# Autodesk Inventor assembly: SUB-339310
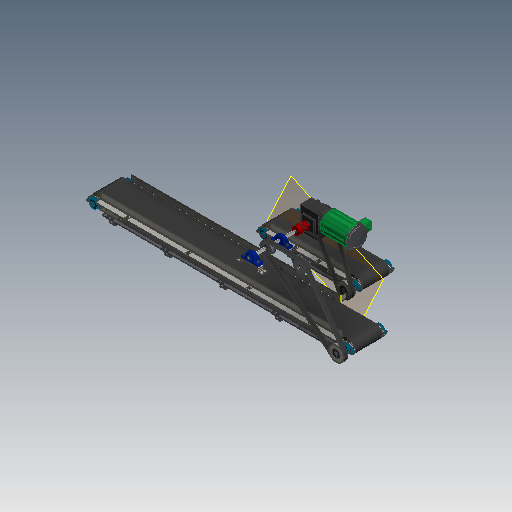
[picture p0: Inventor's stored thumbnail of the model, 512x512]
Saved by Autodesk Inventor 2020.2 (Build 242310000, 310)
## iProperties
Created: 1999-09
Part Number: SUB-339310
Document SubType Name: Assembly
Designer: Autodesk
Mass: 247650 g
Surface Area: 99527.2 cm^2
Volume: 39222.3 cm^3
Density: 6.314 g/cm^3
Control State: 0
Master: False
Checked Out: False
Shininess: 0.0
Length Units: 11269
Angle Units: 11279
Time Units: 11290
Mass Units: 11286
Length Display Precision: 3
Angle Display Precision: 2
Compacted: True
Dimensions: 2353,4x1828,9x1073,3 mm
Mass: 545,974 lb
DocNumber: SUB-339310.iam
Folder: 01 - Themengebiete\Simplification\01 - Packaging machine\
VDS_Category: 3D Komponenten
Density: 0.0
Volumn: 0.0
Area: 0.0
PropertySet Name: Model Information
Author: Autodesk
Revision Number: -
Title: SUB-339310
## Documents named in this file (35)
- D:\07 - DEMODATEN\OTX 2019 - Dataset - UPDATE - Dez2019\Designs\07-Packing machine\SUB-339310.iam
- D:\07 - DEMODATEN\OTX 2019 - Dataset - UPDATE - Dez2019\Designs\07-Packing machine\Parts\ADSK-011842.ipt
- D:\07 - DEMODATEN\OTX 2019 - Dataset - UPDATE - Dez2019\Designs\07-Packing machine\Parts\ADSK-011245.ipt
- D:\07 - DEMODATEN\OTX 2019 - Dataset - UPDATE - Dez2019\Designs\07-Packing machine\Parts\ADSK-011752.ipt
- D:\07 - DEMODATEN\OTX 2019 - Dataset - UPDATE - Dez2019\Designs\07-Packing machine\Parts\ADSK-011796.ipt
- D:\07 - DEMODATEN\OTX 2019 - Dataset - UPDATE - Dez2019\Designs\07-Packing machine\Parts\ADSK-011715.ipt
- D:\07 - DEMODATEN\OTX 2019 - Dataset - UPDATE - Dez2019\Designs\07-Packing machine\Parts\ADSK-011569.ipt
- D:\07 - DEMODATEN\OTX 2019 - Dataset - UPDATE - Dez2019\Designs\07-Packing machine\Parts\ADSK-011567.ipt
- D:\07 - DEMODATEN\OTX 2019 - Dataset - UPDATE - Dez2019\Designs\07-Packing machine\Parts\ADSK-011744.ipt
- D:\07 - DEMODATEN\OTX 2019 - Dataset - UPDATE - Dez2019\Designs\07-Packing machine\Parts\ADSK-011738.ipt
- D:\07 - DEMODATEN\OTX 2019 - Dataset - UPDATE - Dez2019\Designs\07-Packing machine\Parts\ADSK-011775.ipt
- D:\07 - DEMODATEN\OTX 2019 - Dataset - UPDATE - Dez2019\Designs\07-Packing machine\Parts\ADSK-011780.ipt
- D:\07 - DEMODATEN\OTX 2019 - Dataset - UPDATE - Dez2019\Designs\07-Packing machine\A104989.iam
- D:\07 - DEMODATEN\OTX 2019 - Dataset - UPDATE - Dez2019\Designs\07-Packing machine\Parts\ADSK-011703.ipt
- D:\07 - DEMODATEN\OTX 2019 - Dataset - UPDATE - Dez2019\Content Center Files\de-DE\DIN 125-1  B\DIN 125-1 - B 6,4.ipt
- D:\07 - DEMODATEN\OTX 2019 - Dataset - UPDATE - Dez2019\Content Center Files\de-DE\ISO 4762(2)\ISO 4762 - M6 x 20ISO.ipt
- D:\07 - DEMODATEN\OTX 2019 - Dataset - UPDATE - Dez2019\Content Center Files\de-DE\DIN 125-1  B\DIN 125-1 - B 8,4.ipt
- D:\07 - DEMODATEN\OTX 2019 - Dataset - UPDATE - Dez2019\Content Center Files\de-DE\ISO 4032(1)\ISO 4032 - M8DIN EN.ipt
- D:\07 - DEMODATEN\OTX 2019 - Dataset - UPDATE - Dez2019\Content Center Files\de-DE\ISO 4762(2)\ISO 4762 - M8 x 25ISO.ipt
- D:\07 - DEMODATEN\OTX 2019 - Dataset - UPDATE - Dez2019\Content Center Files\de-DE\ISO 4762(2)\ISO 4762 - M8 x 35ISO.ipt
- D:\07 - DEMODATEN\OTX 2019 - Dataset - UPDATE - Dez2019\Designs\07-Packing machine\ADSK-014344.iam
- D:\07 - DEMODATEN\OTX 2019 - Dataset - UPDATE - Dez2019\Content Center Files\de-DE\ISO 2491 - A\ISO 2491 - A  6 x 4 x 45.ipt
- D:\07 - DEMODATEN\OTX 2019 - Dataset - UPDATE - Dez2019\Content Center Files\de-DE\ISO 4762(2)\ISO 4762 - M8 x 40ISO.ipt
- D:\07 - DEMODATEN\OTX 2019 - Dataset - UPDATE - Dez2019\Content Center Files\de-DE\ISO 2338(2)\ISO 2338 - 10 m6 x 24.ipt
- D:\07 - DEMODATEN\OTX 2019 - Dataset - UPDATE - Dez2019\Content Center Files\de-DE\ISO 4026\ISO 4026 - M8 x 25 - ISO.ipt
- D:\07 - DEMODATEN\OTX 2019 - Dataset - UPDATE - Dez2019\Content Center Files\de-DE\ISO 4035(2)\ISO 4035 - M16 - ISO.ipt
- D:\07 - DEMODATEN\OTX 2019 - Dataset - UPDATE - Dez2019\Designs\07-Packing machine\ADSK-014353.iam
- D:\07 - DEMODATEN\OTX 2019 - Dataset - UPDATE - Dez2019\Designs\07-Packing machine\ADSK-014354.iam
- D:\07 - DEMODATEN\OTX 2019 - Dataset - UPDATE - Dez2019\Designs\07-Packing machine\Parts\ADSK-011566.ipt
- D:\07 - DEMODATEN\OTX 2019 - Dataset - UPDATE - Dez2019\Designs\07-Packing machine\Parts\ADSK-011812.ipt
- D:\07 - DEMODATEN\OTX 2019 - Dataset - UPDATE - Dez2019\Content Center Files\de-DE\ISO 4032(1)\ISO 4032 - M6DIN EN.ipt
- D:\07 - DEMODATEN\OTX 2019 - Dataset - UPDATE - Dez2019\Content Center Files\de-DE\ISO 4762(2)\ISO 4762 - M6 x 16ISO.ipt
- D:\07 - DEMODATEN\OTX 2019 - Dataset - UPDATE - Dez2019\Content Center Files\de-DE\ISO 2491 - A\ISO 2491 - A  6 x 4 x 32.ipt
- D:\07 - DEMODATEN\OTX 2019 - Dataset - UPDATE - Dez2019\Designs\07-Packing machine\Parts\ADSK-014368.ipt
- D:\07 - DEMODATEN\OTX 2019 - Dataset - UPDATE - Dez2019\Designs\07-Packing machine\Parts\ADSK-014369.ipt
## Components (170 placed, 34 different names)
1. ADSK-014354:1 [sub-assembly] — Passend:418, Fluchtend:63
2. ADSK-011569:1 — Fluchtend:43, Fluchtend:45, Fluchtend:46, Fluchtend:47, Passend:273, Mate:284
3. ADSK-011569:2 — Fluchtend:44, Fluchtend:45, Fluchtend:46, Passend:267, Passend:268, Passend:269, Passend:270, Fluchtend:49, Fluchtend:54, Passend:294
4. ADSK-011715:1 — Passend:273, Passend:279, Passend:281, Passend:283, Mate:284, Mate:285, Fluchtend:50
5. ADSK-011715:2 — Passend:268, Passend:269, Passend:270, Passend:275, Passend:277, Passend:282
6. ADSK-011796:1 — Fluchtend:48, Passend:282, Fluchtend:49, Passend:295, Passend:307, Passend:308, Passend:309, Passend:417, Passend:419, Passend:421
7. ADSK-011567:1 — Passend:283, Fluchtend:50, Passend:286, Passend:287, Passend:288, Passend:289, Fluchtend:52, Passend:296, Passend:297, Passend:298, Passend:302, Passend:303, Passend:304, Passend:305, Passend:306
8. ADSK-014344:1 [sub-assembly] — Passend:286, Fluchtend:52, Fluchtend:55, Passend:424, Fluchtend:425
9. ADSK-011703:2 — Fluchtend:53, Fluchtend:54, Einfügen:58, Passend:294
10. ADSK-011780:1 — Einfügen:58, Passend:290, Einfügen:62
11. A104989:1 [sub-assembly] — Passend:290, Passend:291, Passend:292, Einfügen:60
12. ADSK-011775:2 — Passend:291, Passend:292, Einfügen:59, Einfügen:61, Fluchtend:55, Passend:423, Fluchtend:424, Fluchtend:425
13. ADSK-011752:1 — Passend:307, Passend:308, Passend:309, Passend:318, Einfügen:67, Einfügen:73
14. ADSK-011744:1 — Passend:295, Winkel:1, Passend:300
15. ADSK-011738:1 — Passend:298, Passend:299, Passend:301, Passend:302
16. ADSK-011744:2 — Passend:296, Passend:297, Passend:299, Winkel:1, Passend:300, Passend:301, Passend:303
17. ADSK-011842:1 — Einfügen:73
18. ADSK-011245:1 — Passend:318, Einfügen:67
19. ADSK-014353:1 [sub-assembly] — Fluchtend:56, Fluchtend:57, Fluchtend:58, Passend:329, Passend:330, Fluchtend:59, Fluchtend:60, Fluchtend:61, Passend:331, Passend:332, Fluchtend:62, Fluchtend:423, Fluchtend:424
20. ADSK-011780:2 — Fluchtend:66
21. A104989:2 [sub-assembly]
22. ADSK-011703:3 — Fluchtend:64, Fluchtend:65
23. ADSK-011775:3 — Einfügen:120, Fluchtend:63, Fluchtend:66, Fluchtend:426, Fluchtend:427
24. ADSK-014344:2 [sub-assembly] — Passend:417, Passend:418, Passend:420, Fluchtend:426
25. ADSK-014368:1 — Fluchtend:423, Passend:423, Passend:424
26. ADSK-014369:1 — Fluchtend:427
27. DIN 125-1 B B 8,4:30
28. ISO 4762 M8 x 40:2
29. ISO 2338 10 m6 x 24:3
30. ISO 2338 10 m6 x 24:4
31. ISO 4026 M8 x 25:2 — Einfügen:120
32. ISO 4035 M16:2
33. ISO 2491 A A  6 x 4 x 32:1 — Passend:419, Passend:420, Passend:421
34. DIN 125-1 B B 6,4:22 — Passend:335
35. DIN 125-1 B B 6,4:23 — Passend:337
36. DIN 125-1 B B 6,4:24 — Passend:339
37. DIN 125-1 B B 6,4:25 — Passend:341
38. DIN 125-1 B B 6,4:26 — Passend:343
39. DIN 125-1 B B 6,4:27 — Passend:345
40. DIN 125-1 B B 6,4:28 — Passend:347
41. DIN 125-1 B B 6,4:29 — Passend:349
42. DIN 125-1 B B 6,4:30 — Passend:351
43. DIN 125-1 B B 6,4:31 — Passend:353
44. DIN 125-1 B B 6,4:32 — Passend:355
45. DIN 125-1 B B 6,4:33 — Passend:357
46. DIN 125-1 B B 6,4:34 — Passend:359
47. DIN 125-1 B B 6,4:35 — Passend:361
48. DIN 125-1 B B 6,4:36 — Passend:363
49. DIN 125-1 B B 6,4:37 — Passend:365
50. DIN 125-1 B B 6,4:38 — Passend:367
51. DIN 125-1 B B 6,4:39 — Passend:369
52. DIN 125-1 B B 6,4:40 — Passend:371
53. DIN 125-1 B B 6,4:41 — Passend:373
54. DIN 125-1 B B 6,4:42
55. DIN 125-1 B B 6,4:43
56. DIN 125-1 B B 6,4:44
57. DIN 125-1 B B 6,4:45
58. DIN 125-1 B B 6,4:46
59. DIN 125-1 B B 6,4:47
60. DIN 125-1 B B 6,4:48
61. DIN 125-1 B B 6,4:49
62. DIN 125-1 B B 6,4:50
63. DIN 125-1 B B 6,4:51
64. DIN 125-1 B B 6,4:52
65. DIN 125-1 B B 6,4:53
66. DIN 125-1 B B 6,4:54
67. DIN 125-1 B B 6,4:55
68. DIN 125-1 B B 6,4:56 — Passend:375, Passend:377, Passend:379, Passend:381, Passend:383, Passend:385, Passend:387, Passend:389, Passend:391, Passend:393, Passend:395, Passend:397, Passend:399, Passend:401, Passend:403, Passend:405, Passend:407, Passend:409, Passend:411, Passend:413
69. DIN 125-1 B B 6,4:57
70. DIN 125-1 B B 6,4:58
71. DIN 125-1 B B 6,4:59
72. DIN 125-1 B B 6,4:60
73. DIN 125-1 B B 6,4:61
74. DIN EN 24032 M6:1
75. DIN EN 24032 M6:2
76. DIN EN 24032 M6:3
77. DIN EN 24032 M6:4
78. DIN EN 24032 M6:5
79. DIN EN 24032 M6:6
80. DIN EN 24032 M6:7
81. DIN EN 24032 M6:8
82. DIN EN 24032 M6:9
83. DIN EN 24032 M6:10
84. DIN EN 24032 M6:11
85. DIN EN 24032 M6:12
86. DIN EN 24032 M6:13
87. DIN EN 24032 M6:14
88. DIN EN 24032 M6:15
89. DIN EN 24032 M6:16
90. DIN EN 24032 M6:17
91. DIN EN 24032 M6:18
92. DIN EN 24032 M6:19
93. DIN EN 24032 M6:20
94. ISO 4762 M6 x 16:1 — Passend:375
95. ISO 4762 M6 x 16:2 — Passend:377
96. ISO 4762 M6 x 16:3 — Passend:379
97. ISO 4762 M6 x 16:4 — Passend:381
98. ISO 4762 M6 x 16:5 — Passend:383
99. ISO 4762 M6 x 16:6 — Passend:385
100. ISO 4762 M6 x 16:7 — Passend:387
101. ISO 4762 M6 x 16:8 — Passend:389
102. ISO 4762 M6 x 16:9 — Passend:391
103. ISO 4762 M6 x 16:10 — Passend:393
104. ISO 4762 M6 x 16:11 — Passend:395
105. ISO 4762 M6 x 16:12 — Passend:397
106. ISO 4762 M6 x 16:13 — Passend:399
107. ISO 4762 M6 x 16:14 — Passend:401
108. ISO 4762 M6 x 16:15 — Passend:403
109. ISO 4762 M6 x 16:16 — Passend:405
110. ISO 4762 M6 x 16:17 — Passend:407
111. ISO 4762 M6 x 16:18 — Passend:409
112. ISO 4762 M6 x 16:19 — Passend:411
113. ISO 4762 M6 x 16:20 — Passend:413
114. DIN 125-1 B B 8,4:26
115. DIN 125-1 B B 8,4:27 — Passend:311, Passend:313, Passend:315, Passend:317
116. DIN 125-1 B B 8,4:28
117. DIN 125-1 B B 8,4:29
118. ISO 4762 M8 x 25:9 — Passend:311
119. ISO 4762 M8 x 25:10 — Passend:313
120. ISO 4762 M8 x 25:11 — Passend:315
121. ISO 4762 M8 x 25:12 — Passend:317
122. DIN 125-1 B B 6,4:17 — Passend:320, Passend:322, Passend:324, Passend:326, Passend:328
123. DIN 125-1 B B 6,4:18
124. DIN 125-1 B B 6,4:19
125. DIN 125-1 B B 6,4:20
126. DIN 125-1 B B 6,4:21
127. ISO 4762 M6 x 20:9 — Passend:320
128. ISO 4762 M6 x 20:10 — Passend:322
129. ISO 4762 M6 x 20:11 — Passend:324
130. ISO 4762 M6 x 20:12 — Passend:326
131. ISO 4762 M6 x 20:13 — Passend:328
132. ISO 2491 A A  6 x 4 x 45:2 — Passend:304, Passend:305, Passend:306
133. ISO 4035 M16:1 — Einfügen:62
134. DIN 125-1 B B 8,4:25
135. ISO 4762 M8 x 40:1
136. ISO 2338 10 m6 x 24:1 — Einfügen:60
137. ISO 2338 10 m6 x 24:2 — Einfügen:59
138. ISO 4026 M8 x 25:1 — Einfügen:61
139. ISO 2491 A A  6 x 4 x 45:1 — Passend:287, Passend:288, Passend:289
140. DIN 125-1 B B 8,4:17 — Passend:275
141. DIN 125-1 B B 8,4:18 — Passend:277
142. DIN 125-1 B B 8,4:19 — Passend:279
143. DIN 125-1 B B 8,4:20 — Passend:281
144. DIN 125-1 B B 8,4:21
145. DIN 125-1 B B 8,4:22
146. DIN 125-1 B B 8,4:23
147. DIN 125-1 B B 8,4:24
148. DIN EN 24032 M8:13
149. DIN EN 24032 M8:14
150. DIN EN 24032 M8:15
151. DIN EN 24032 M8:16
152. ISO 4762 M8 x 35:1
153. ISO 4762 M8 x 35:2 — Mate:285
154. ISO 4762 M8 x 35:3
155. ISO 4762 M8 x 35:4
156. ADSK-011566:2 — Passend:330, Fluchtend:59, Passend:331
157. ADSK-011566:1 — Passend:329, Fluchtend:60, Fluchtend:61, Passend:333, Passend:335, Passend:337, Passend:339, Passend:341, Passend:343, Passend:345, Passend:347, Passend:349, Passend:351, Passend:353, Passend:355, Passend:357, Passend:359, Passend:361, Passend:363, Passend:365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
158. ADSK-011812:1 — Passend:332, Passend:333, Fluchtend:62
159. ADSK-011566:3
160. ADSK-011566:4
161. ADSK-011812:2
162. ADSK-011566:5
163. ADSK-011566:6
164. ADSK-011812:3
165. ADSK-011566:7
166. ADSK-011566:8
167. ADSK-011812:4
168. ADSK-011566:9
169. ADSK-011566:10
170. ADSK-011812:5
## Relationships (135: Mate 98, Flush 28, Insert 8, Angle 1)
- Fluchtend:43 [Flush]: ADSK-011569:1
- Fluchtend:44 [Flush]: ADSK-011569:2
- Fluchtend:45 [Flush]: ADSK-011569:1 ↔ ADSK-011569:2
- Fluchtend:46 [Flush]: ADSK-011569:1 ↔ ADSK-011569:2
- Fluchtend:47 [Flush]: ADSK-011569:1
- Passend:267 [Mate]: ADSK-011569:2
- Passend:268 [Mate]: ADSK-011569:2 ↔ ADSK-011715:2
- Passend:269 [Mate]: ADSK-011569:2 ↔ ADSK-011715:2
- Passend:270 [Mate]: ADSK-011569:2 ↔ ADSK-011715:2
- Passend:273 [Mate]: ADSK-011569:1 ↔ ADSK-011715:1
- Passend:275 [Mate]: ADSK-011715:2 ↔ DIN 125-1 B B 8,4:17
- Passend:277 [Mate]: ADSK-011715:2 ↔ DIN 125-1 B B 8,4:18
- Passend:279 [Mate]: ADSK-011715:1 ↔ DIN 125-1 B B 8,4:19
- Passend:281 [Mate]: ADSK-011715:1 ↔ DIN 125-1 B B 8,4:20
- Fluchtend:48 [Flush]: ADSK-011796:1
- Passend:282 [Mate]: ADSK-011715:2 ↔ ADSK-011796:1
- Fluchtend:49 [Flush]: ADSK-011569:2 ↔ ADSK-011796:1
- Passend:283 [Mate]: ADSK-011715:1 ↔ ADSK-011567:1
- Mate:284: ADSK-011569:1 ↔ ADSK-011715:1
- Mate:285: ADSK-011715:1 ↔ ISO 4762 M8 x 35:2
- Fluchtend:50 [Flush]: ADSK-011715:1 ↔ ADSK-011567:1
- Passend:286 [Mate]: ADSK-011567:1 ↔ ADSK-014344:1
- Passend:287 [Mate]: ADSK-011567:1 ↔ ISO 2491 A A  6 x 4 x 45:1
- Passend:288 [Mate]: ADSK-011567:1 ↔ ISO 2491 A A  6 x 4 x 45:1
- Passend:289 [Mate]: ADSK-011567:1 ↔ ISO 2491 A A  6 x 4 x 45:1
- Fluchtend:52 [Flush]: ADSK-011567:1 ↔ ADSK-014344:1
- Fluchtend:53 [Flush]: ADSK-011703:2
- Fluchtend:54 [Flush]: ADSK-011569:2 ↔ ADSK-011703:2
- Einfügen:58 [Insert]: ADSK-011703:2 ↔ ADSK-011780:1
- Passend:290 [Mate]: ADSK-011780:1 ↔ A104989:1
- Passend:291 [Mate]: A104989:1 ↔ ADSK-011775:2
- Passend:292 [Mate]: A104989:1 ↔ ADSK-011775:2
- Einfügen:59 [Insert]: ADSK-011775:2 ↔ ISO 2338 10 m6 x 24:2
- Einfügen:60 [Insert]: A104989:1 ↔ ISO 2338 10 m6 x 24:1
- Einfügen:61 [Insert]: ADSK-011775:2 ↔ ISO 4026 M8 x 25:1
- Fluchtend:55 [Flush]: ADSK-014344:1 ↔ ADSK-011775:2
- Einfügen:62 [Insert]: ADSK-011780:1 ↔ ISO 4035 M16:1
- Passend:294 [Mate]: ADSK-011569:2 ↔ ADSK-011703:2
- Passend:295 [Mate]: ADSK-011796:1 ↔ ADSK-011744:1
- Passend:296 [Mate]: ADSK-011567:1 ↔ ADSK-011744:2
- Passend:297 [Mate]: ADSK-011567:1 ↔ ADSK-011744:2
- Passend:298 [Mate]: ADSK-011567:1 ↔ ADSK-011738:1
- Passend:299 [Mate]: ADSK-011738:1 ↔ ADSK-011744:2
- Winkel:1 [Angle]: ADSK-011744:1 ↔ ADSK-011744:2
- Passend:300 [Mate]: ADSK-011744:1 ↔ ADSK-011744:2
- Passend:301 [Mate]: ADSK-011738:1 ↔ ADSK-011744:2
- Passend:302 [Mate]: ADSK-011567:1 ↔ ADSK-011738:1
- Passend:303 [Mate]: ADSK-011567:1 ↔ ADSK-011744:2
- Passend:304 [Mate]: ADSK-011567:1 ↔ ISO 2491 A A  6 x 4 x 45:2
- Passend:305 [Mate]: ADSK-011567:1 ↔ ISO 2491 A A  6 x 4 x 45:2
- Passend:306 [Mate]: ADSK-011567:1 ↔ ISO 2491 A A  6 x 4 x 45:2
- Passend:307 [Mate]: ADSK-011796:1 ↔ ADSK-011752:1
- Passend:308 [Mate]: ADSK-011796:1 ↔ ADSK-011752:1
- Passend:309 [Mate]: ADSK-011796:1 ↔ ADSK-011752:1
- Passend:311 [Mate]: DIN 125-1 B B 8,4:27 ↔ ISO 4762 M8 x 25:9
- Passend:313 [Mate]: DIN 125-1 B B 8,4:27 ↔ ISO 4762 M8 x 25:10
- Passend:315 [Mate]: DIN 125-1 B B 8,4:27 ↔ ISO 4762 M8 x 25:11
- Passend:317 [Mate]: DIN 125-1 B B 8,4:27 ↔ ISO 4762 M8 x 25:12
- Passend:318 [Mate]: ADSK-011752:1 ↔ ADSK-011245:1
- Einfügen:67 [Insert]: ADSK-011752:1 ↔ ADSK-011245:1
- Passend:320 [Mate]: DIN 125-1 B B 6,4:17 ↔ ISO 4762 M6 x 20:9
- Passend:322 [Mate]: DIN 125-1 B B 6,4:17 ↔ ISO 4762 M6 x 20:10
- Passend:324 [Mate]: DIN 125-1 B B 6,4:17 ↔ ISO 4762 M6 x 20:11
- Passend:326 [Mate]: DIN 125-1 B B 6,4:17 ↔ ISO 4762 M6 x 20:12
- Passend:328 [Mate]: DIN 125-1 B B 6,4:17 ↔ ISO 4762 M6 x 20:13
- Einfügen:73 [Insert]: ADSK-011752:1 ↔ ADSK-011842:1
- Fluchtend:56 [Flush]: ADSK-014353:1
- Fluchtend:57 [Flush]: ADSK-014353:1
- Fluchtend:58 [Flush]: ADSK-014353:1
- Passend:329 [Mate]: ADSK-014353:1 ↔ ADSK-011566:1
- Passend:330 [Mate]: ADSK-014353:1 ↔ ADSK-011566:2
- Fluchtend:59 [Flush]: ADSK-014353:1 ↔ ADSK-011566:2
- Fluchtend:60 [Flush]: ADSK-014353:1 ↔ ADSK-011566:1
- Fluchtend:61 [Flush]: ADSK-014353:1 ↔ ADSK-011566:1
- Passend:331 [Mate]: ADSK-014353:1 ↔ ADSK-011566:2
- Passend:332 [Mate]: ADSK-014353:1 ↔ ADSK-011812:1
- Passend:333 [Mate]: ADSK-011566:1 ↔ ADSK-011812:1
- Fluchtend:62 [Flush]: ADSK-014353:1 ↔ ADSK-011812:1
- Passend:335 [Mate]: DIN 125-1 B B 6,4:22 ↔ ADSK-011566:1
- Passend:337 [Mate]: DIN 125-1 B B 6,4:23 ↔ ADSK-011566:1
- Passend:339 [Mate]: DIN 125-1 B B 6,4:24 ↔ ADSK-011566:1
- Passend:341 [Mate]: DIN 125-1 B B 6,4:25 ↔ ADSK-011566:1
- Passend:343 [Mate]: DIN 125-1 B B 6,4:26 ↔ ADSK-011566:1
- Passend:345 [Mate]: DIN 125-1 B B 6,4:27 ↔ ADSK-011566:1
- Passend:347 [Mate]: DIN 125-1 B B 6,4:28 ↔ ADSK-011566:1
- Passend:349 [Mate]: DIN 125-1 B B 6,4:29 ↔ ADSK-011566:1
- Passend:351 [Mate]: DIN 125-1 B B 6,4:30 ↔ ADSK-011566:1
- Passend:353 [Mate]: DIN 125-1 B B 6,4:31 ↔ ADSK-011566:1
- Passend:355 [Mate]: DIN 125-1 B B 6,4:32 ↔ ADSK-011566:1
- Passend:357 [Mate]: DIN 125-1 B B 6,4:33 ↔ ADSK-011566:1
- Passend:359 [Mate]: DIN 125-1 B B 6,4:34 ↔ ADSK-011566:1
- Passend:361 [Mate]: DIN 125-1 B B 6,4:35 ↔ ADSK-011566:1
- Passend:363 [Mate]: DIN 125-1 B B 6,4:36 ↔ ADSK-011566:1
- Passend:365 [Mate]: DIN 125-1 B B 6,4:37 ↔ ADSK-011566:1
- Passend:367 [Mate]: DIN 125-1 B B 6,4:38 ↔ ADSK-011566:1
- Passend:369 [Mate]: DIN 125-1 B B 6,4:39 ↔ ADSK-011566:1
- Passend:371 [Mate]: DIN 125-1 B B 6,4:40 ↔ ADSK-011566:1
- Passend:373 [Mate]: DIN 125-1 B B 6,4:41 ↔ ADSK-011566:1
- Passend:375 [Mate]: DIN 125-1 B B 6,4:56 ↔ ISO 4762 M6 x 16:1
- Passend:377 [Mate]: DIN 125-1 B B 6,4:56 ↔ ISO 4762 M6 x 16:2
- Passend:379 [Mate]: DIN 125-1 B B 6,4:56 ↔ ISO 4762 M6 x 16:3
- Passend:381 [Mate]: DIN 125-1 B B 6,4:56 ↔ ISO 4762 M6 x 16:4
- Passend:383 [Mate]: DIN 125-1 B B 6,4:56 ↔ ISO 4762 M6 x 16:5
- Passend:385 [Mate]: DIN 125-1 B B 6,4:56 ↔ ISO 4762 M6 x 16:6
- Passend:387 [Mate]: DIN 125-1 B B 6,4:56 ↔ ISO 4762 M6 x 16:7
- Passend:389 [Mate]: DIN 125-1 B B 6,4:56 ↔ ISO 4762 M6 x 16:8
- Passend:391 [Mate]: DIN 125-1 B B 6,4:56 ↔ ISO 4762 M6 x 16:9
- Passend:393 [Mate]: DIN 125-1 B B 6,4:56 ↔ ISO 4762 M6 x 16:10
- Passend:395 [Mate]: DIN 125-1 B B 6,4:56 ↔ ISO 4762 M6 x 16:11
- Passend:397 [Mate]: DIN 125-1 B B 6,4:56 ↔ ISO 4762 M6 x 16:12
- Passend:399 [Mate]: DIN 125-1 B B 6,4:56 ↔ ISO 4762 M6 x 16:13
- Passend:401 [Mate]: DIN 125-1 B B 6,4:56 ↔ ISO 4762 M6 x 16:14
- Passend:403 [Mate]: DIN 125-1 B B 6,4:56 ↔ ISO 4762 M6 x 16:15
- Passend:405 [Mate]: DIN 125-1 B B 6,4:56 ↔ ISO 4762 M6 x 16:16
- Passend:407 [Mate]: DIN 125-1 B B 6,4:56 ↔ ISO 4762 M6 x 16:17
- Passend:409 [Mate]: DIN 125-1 B B 6,4:56 ↔ ISO 4762 M6 x 16:18
- Passend:411 [Mate]: DIN 125-1 B B 6,4:56 ↔ ISO 4762 M6 x 16:19
- Passend:413 [Mate]: DIN 125-1 B B 6,4:56 ↔ ISO 4762 M6 x 16:20
- Passend:417 [Mate]: ADSK-011796:1 ↔ ADSK-014344:2
- Passend:418 [Mate]: ADSK-014354:1 ↔ ADSK-014344:2
- Passend:419 [Mate]: ADSK-011796:1 ↔ ISO 2491 A A  6 x 4 x 32:1
- Passend:420 [Mate]: ADSK-014344:2 ↔ ISO 2491 A A  6 x 4 x 32:1
- Passend:421 [Mate]: ADSK-011796:1 ↔ ISO 2491 A A  6 x 4 x 32:1
- Einfügen:120 [Insert]: ADSK-011775:3 ↔ ISO 4026 M8 x 25:2
- Fluchtend:63 [Flush]: ADSK-014354:1 ↔ ADSK-011775:3
- Fluchtend:64 [Flush]: ADSK-011703:3
- Fluchtend:65 [Flush]: ADSK-011703:3
- Fluchtend:66 [Flush]: ADSK-011780:2 ↔ ADSK-011775:3
- Fluchtend:423 [Flush]: ADSK-014353:1 ↔ ADSK-014368:1
- Passend:423 [Mate]: ADSK-011775:2 ↔ ADSK-014368:1
- Passend:424 [Mate]: ADSK-014344:1 ↔ ADSK-014368:1
- Fluchtend:424 [Flush]: ADSK-011775:2 ↔ ADSK-014353:1
- Fluchtend:425 [Flush]: ADSK-014344:1 ↔ ADSK-011775:2
- Fluchtend:426 [Flush]: ADSK-011775:3 ↔ ADSK-014344:2
- Fluchtend:427 [Flush]: ADSK-011775:3 ↔ ADSK-014369:1
## Named parameters: d1102_d877 = 0, d1103_d878 = 0, d1104_d879 = 0, d1105_d881 = 0, d1106_d882 = 0, d1107_d883 = 0, d1108_d884 = 0, d1109_d885 = 0, d1110_d895 = 0
